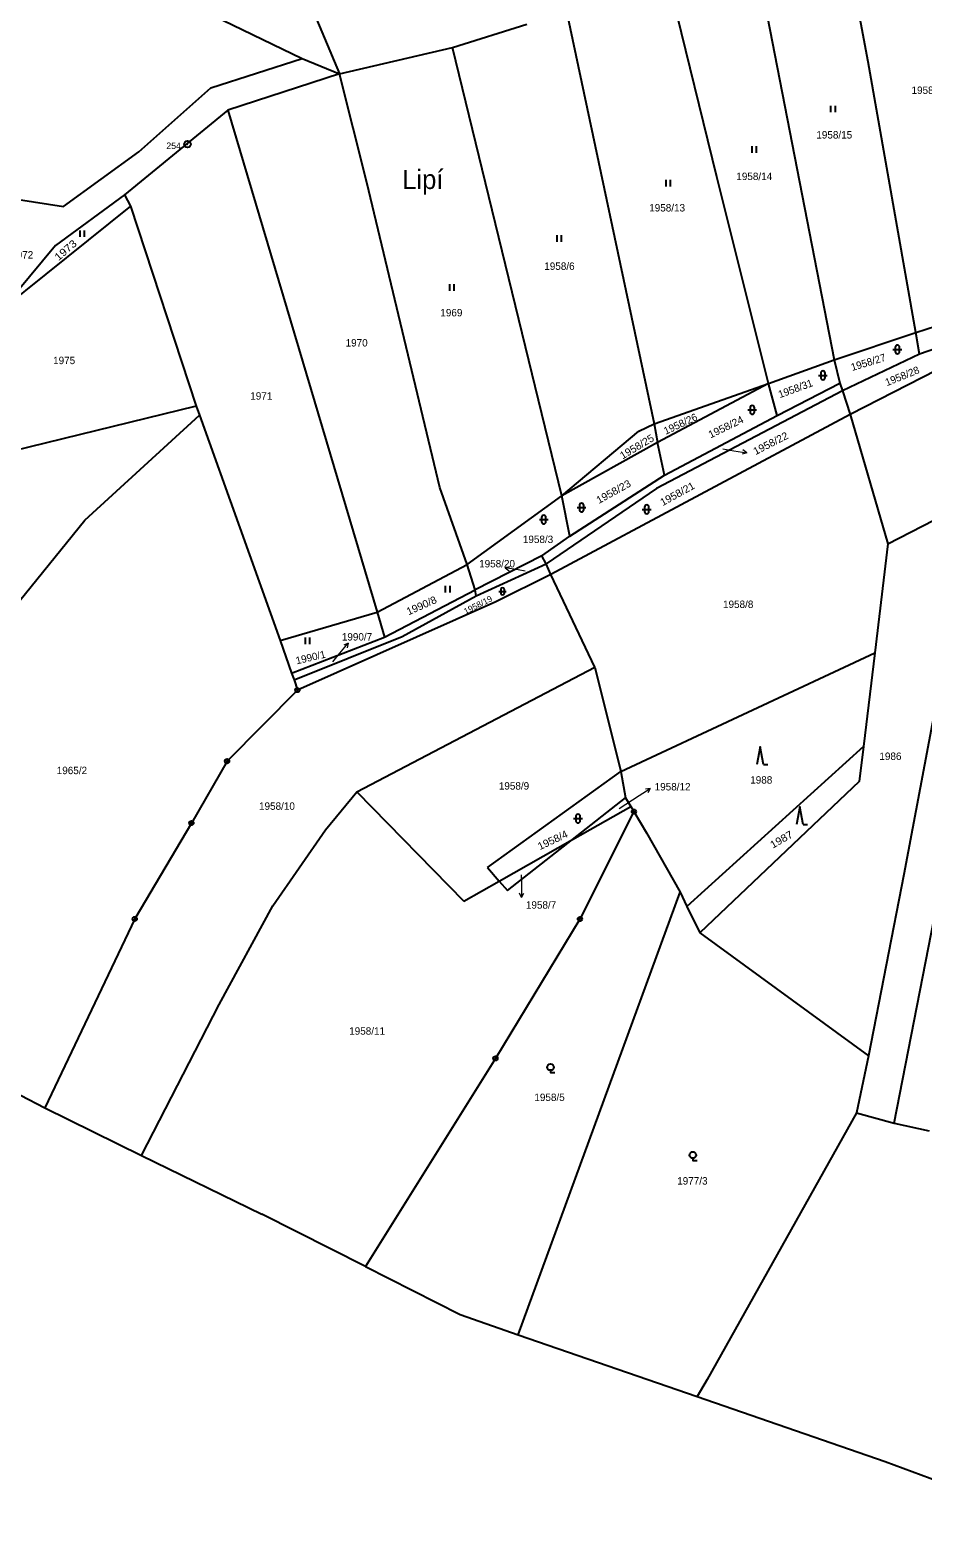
# Model space of a CAD drawing. Extents: x -820420 to -815896, y -1105820 to -1103643.
# Drawn here: x -817820.3 to -817615.8, y -1105643.5 to -1105298 of the extents above; entities that cross this region are included whole.
import ezdxf
from ezdxf.enums import TextEntityAlignment as Align

# ---------------------------------------------------------------- set-up
doc = ezdxf.new("R2010")
doc.units = 0
doc.header["$LTSCALE"] = 0.68
for name, color, linetype, lineweight in [('1', 7, 'Continuous', 25), ('3', 7, 'Continuous', 25), ('7', 7, 'Continuous', 13), ('8', 7, 'Continuous', 25)]:
    doc.layers.add(name, color=color, linetype=linetype, lineweight=lineweight)
doc.layers.add('2', color=7, linetype='Continuous')

msp = doc.modelspace()

# ---------------------------------------------------------------- linework, layer by layer
at = {"layer": '1'}
for p, q in [((-817770.8, -1105257.05), (-817749.4, -1105308.01)), ((-817628.28, -1105305.24), (-817636.42, -1105261.82)), ((-817662.95, -1105331.59), (-817675.54, -1105280.33)), ((-817803.5, -1105282.4), (-817758.02, -1105304.52)), ((-817697.9, -1105291.5), (-817677.3, -1105388.24)), ((-817723.54, -1105302), (-817706.51, -1105296.61)), ((-817749.4, -1105308.01), (-817723.54, -1105302)), ((-817698.51, -1105404.68), (-817723.54, -1105302)), ((-817778.95, -1105311.22), (-817758.02, -1105304.52)), ((-817758.02, -1105304.52), (-817749.4, -1105308.01)), ((-817617.36, -1105367.25), (-817628.28, -1105305.24)), ((-817749.4, -1105308.01), (-817775.03, -1105316.3)), ((-817743.19, -1105332.91), (-817749.4, -1105308.01)), ((-817795.42, -1105325.91), (-817778.95, -1105311.22)), ((-817775.03, -1105316.3), (-817798.7, -1105335.71)), ((-817775.03, -1105316.3), (-817740.83, -1105431.41)), ((-817812.7, -1105338.43), (-817795.42, -1105325.91)), ((-817726.41, -1105402.79), (-817743.19, -1105332.91)), ((-817651.1, -1105378.94), (-817662.95, -1105331.59)), ((-817823, -1105336.84), (-817812.7, -1105338.43)), ((-817798.7, -1105335.71), (-817814.49, -1105347.38)), ((-817798.7, -1105335.71), (-817797.31, -1105338.32)), ((-817797.31, -1105338.32), (-817826.4, -1105361.74)), ((-817797.31, -1105338.32), (-817782.25, -1105384.13)), ((-817814.49, -1105347.38), (-817826.4, -1105361.74)), ((-817617.36, -1105367.25), (-817592.59, -1105359.31)), ((-817592.07, -1105363.77), (-817616.48, -1105372.23)), ((-817636.05, -1105373.55), (-817617.36, -1105367.25)), ((-817616.48, -1105372.23), (-817617.36, -1105367.25)), ((-817651.1, -1105378.94), (-817636.05, -1105373.55)), ((-817616.48, -1105372.23), (-817634.14, -1105380.66)), ((-817609.28, -1105374.23), (-817632.39, -1105386.09)), ((-817649.14, -1105386.32), (-817634.78, -1105378.88)), ((-817634.78, -1105378.88), (-817634.14, -1105380.66)), ((-817677.3, -1105388.24), (-817651.1, -1105378.94)), ((-817634.14, -1105380.66), (-817676.81, -1105403.03)), ((-817651.1, -1105378.94), (-817676.56, -1105392.48)), ((-817649.14, -1105386.32), (-817651.1, -1105378.94)), ((-817634.14, -1105380.66), (-817632.39, -1105386.09)), ((-817782.25, -1105384.13), (-817857.97, -1105402.72)), ((-817782.25, -1105384.13), (-817781.55, -1105386.25)), ((-817807.78, -1105410.27), (-817781.55, -1105386.25)), ((-817781.55, -1105386.25), (-817763.01, -1105437.87)), ((-817632.39, -1105386.09), (-817700.97, -1105422.74)), ((-817680.87, -1105389.9), (-817677.3, -1105388.24)), ((-817677.3, -1105388.24), (-817676.56, -1105392.48)), ((-817674.95, -1105399.99), (-817649.14, -1105386.32)), ((-817632.39, -1105386.09), (-817623.79, -1105415.7)), ((-817698.51, -1105404.68), (-817680.87, -1105389.9)), ((-817676.56, -1105392.48), (-817698.51, -1105404.68)), ((-817674.95, -1105399.99), (-817676.56, -1105392.48)), ((-817720.2, -1105420.42), (-817726.41, -1105402.79)), ((-817676.81, -1105403.03), (-817702.11, -1105420.3)), ((-817696.66, -1105413.94), (-817674.95, -1105399.99)), ((-817720.2, -1105420.42), (-817698.51, -1105404.68)), ((-817696.66, -1105413.94), (-817698.51, -1105404.68)), ((-817623.79, -1105415.7), (-817603.95, -1105405.51)), ((-817603.95, -1105405.51), (-817620.11, -1105491.48)), ((-817825.59, -1105432.28), (-817807.78, -1105410.27)), ((-817703.07, -1105418.5), (-817696.66, -1105413.94)), ((-817623.79, -1105415.7), (-817626.73, -1105440.73)), ((-817703.07, -1105418.5), (-817718.33, -1105426.29)), ((-817718.08, -1105427.61), (-817702.11, -1105420.3)), ((-817702.11, -1105420.3), (-817703.07, -1105418.5)), ((-817700.97, -1105422.74), (-817702.11, -1105420.3)), ((-817740.83, -1105431.41), (-817720.2, -1105420.42)), ((-817718.33, -1105426.29), (-817720.2, -1105420.42)), ((-817700.97, -1105422.74), (-817713.64, -1105429.02)), ((-817690.91, -1105443.96), (-817700.97, -1105422.74)), ((-817718.08, -1105427.61), (-817718.33, -1105426.29)), ((-817713.64, -1105429.02), (-817759.09, -1105449.24)), ((-817735.11, -1105436.92), (-817718.08, -1105427.61)), ((-817763.01, -1105437.87), (-817740.83, -1105431.41)), ((-817740.83, -1105431.41), (-817739.13, -1105437.14)), ((-817759.81, -1105446.9), (-817735.11, -1105436.92)), ((-817763.01, -1105437.87), (-817760.41, -1105445.32)), ((-817684.95, -1105467.92), (-817626.73, -1105440.73)), ((-817626.73, -1105440.73), (-817629.37, -1105462.17)), ((-817745.5, -1105472.51), (-817690.91, -1105443.96)), ((-817690.91, -1105443.96), (-817684.95, -1105467.92)), ((-817759.09, -1105449.24), (-817775.21, -1105465.52)), ((-817622.3, -1105548.46), (-817604.55, -1105457.26)), ((-817629.37, -1105462.17), (-817669.86, -1105498.83)), ((-817629.37, -1105462.17), (-817630.37, -1105470.21)), ((-817775.21, -1105465.52), (-817783.38, -1105479.69)), ((-817715.53, -1105489.87), (-817684.95, -1105467.92)), ((-817684.95, -1105467.92), (-817683.89, -1105473.93)), ((-817630.37, -1105470.21), (-817666.89, -1105504.89)), ((-817752.68, -1105481.28), (-817745.5, -1105472.51)), ((-817745.5, -1105472.51), (-817720.91, -1105497.58)), ((-817696.06, -1105483.49), (-817683.89, -1105473.93)), ((-817683.89, -1105473.93), (-817682.67, -1105475.9)), ((-817696.06, -1105483.49), (-817682.67, -1105475.9)), ((-817681.95, -1105477.08), (-817694.33, -1105501.71)), ((-817682.67, -1105475.9), (-817681.95, -1105477.08)), ((-817681.95, -1105477.08), (-817679.05, -1105481.94)), ((-817783.38, -1105479.69), (-817796.35, -1105501.67)), ((-817764.68, -1105498.65), (-817752.68, -1105481.28)), ((-817679.05, -1105481.94), (-817671.37, -1105495.53)), ((-817712.82, -1105492.99), (-817696.06, -1105483.49)), ((-817710.93, -1105495.17), (-817696.06, -1105483.49)), ((-817715.53, -1105489.87), (-817712.82, -1105492.99)), ((-817620.11, -1105491.48), (-817628.17, -1105533.03)), ((-817720.91, -1105497.58), (-817712.82, -1105492.99)), ((-817712.82, -1105492.99), (-817710.93, -1105495.17)), ((-817708.49, -1105596.94), (-817671.37, -1105495.53)), ((-817671.37, -1105495.53), (-817669.86, -1105498.83)), ((-817777.02, -1105521.29), (-817764.68, -1105498.65)), ((-817669.86, -1105498.83), (-817666.89, -1105504.89)), ((-817796.35, -1105501.67), (-817816.97, -1105544.94)), ((-817694.33, -1105501.71), (-817713.69, -1105533.64)), ((-817666.89, -1105504.89), (-817628.17, -1105533.03)), ((-817794.81, -1105555.85), (-817777.02, -1105521.29)), ((-817844.82, -1105530.45), (-817816.97, -1105544.94)), ((-817713.69, -1105533.64), (-817743.47, -1105581.35)), ((-817628.17, -1105533.03), (-817630.93, -1105546.11)), ((-817816.97, -1105544.94), (-817794.81, -1105555.85)), ((-817630.93, -1105546.11), (-817665.17, -1105607.22)), ((-817630.93, -1105546.11), (-817622.3, -1105548.46)), ((-817622.3, -1105548.46), (-817614.32, -1105550.25)), ((-817794.81, -1105555.85), (-817767.22, -1105569.35)), ((-817743.47, -1105581.35), (-817767.22, -1105569.35)), ((-817743.47, -1105581.35), (-817721.77, -1105592.34)), ((-817721.77, -1105592.34), (-817708.49, -1105596.94)), ((-817708.49, -1105596.94), (-817667.45, -1105611.14)), ((-817665.17, -1105607.22), (-817667.45, -1105611.14)), ((-817667.45, -1105611.14), (-817624.36, -1105625.97)), ((-817624.36, -1105625.97), (-817577.74, -1105643.5))]:
    msp.add_line(p, q, dxfattribs=at)
for points in [[(-817655.9, -1105271.52), (-817636.05, -1105373.55), (-817634.78, -1105378.88)], [(-817760.41, -1105445.32), (-817739.13, -1105437.14), (-817718.33, -1105426.29)], [(-817760.41, -1105445.32), (-817759.81, -1105446.9), (-817759.09, -1105449.24)]]:
    msp.add_lwpolyline(points, dxfattribs=at)
at = {"layer": '3'}
for p, q in [((-817636.801, -1105316.83), (-817636.801, -1105315.33)), ((-817635.8, -1105316.83), (-817635.8, -1105315.33)), ((-817654.901, -1105326.12), (-817654.901, -1105324.62)), ((-817653.9, -1105326.12), (-817653.9, -1105324.62)), ((-817674.581, -1105333.81), (-817674.581, -1105332.31)), ((-817673.58, -1105333.81), (-817673.58, -1105332.31)), ((-817808.871, -1105345.4), (-817808.871, -1105343.9)), ((-817807.87, -1105345.4), (-817807.87, -1105343.9)), ((-817699.541, -1105346.47), (-817699.541, -1105344.97)), ((-817698.54, -1105346.47), (-817698.54, -1105344.97)), ((-817724.181, -1105357.72), (-817724.181, -1105356.22)), ((-817723.18, -1105357.72), (-817723.18, -1105356.22)), ((-817622.591, -1105371.161), (-817620.589, -1105371.161)), ((-817622.091, -1105370.661), (-817622.091, -1105371.662)), ((-817621.089, -1105371.662), (-817621.089, -1105370.661)), ((-817639.651, -1105377.101), (-817637.649, -1105377.101)), ((-817639.151, -1105376.601), (-817639.151, -1105377.602)), ((-817638.149, -1105377.602), (-817638.149, -1105376.601)), ((-817655.861, -1105385.031), (-817653.859, -1105385.031)), ((-817655.361, -1105384.531), (-817655.361, -1105385.532)), ((-817654.359, -1105385.532), (-817654.359, -1105384.531)), ((-817703.121, -1105409.651), (-817703.121, -1105410.652)), ((-817702.119, -1105410.652), (-817702.119, -1105409.651)), ((-817694.971, -1105407.411), (-817692.969, -1105407.411)), ((-817694.471, -1105406.911), (-817694.471, -1105407.912)), ((-817693.469, -1105407.912), (-817693.469, -1105406.911)), ((-817680.041, -1105407.811), (-817678.039, -1105407.811)), ((-817679.541, -1105407.311), (-817679.541, -1105408.312)), ((-817678.539, -1105408.312), (-817678.539, -1105407.311)), ((-817703.621, -1105410.151), (-817701.619, -1105410.151)), ((-817725.111, -1105426.84), (-817725.111, -1105425.34)), ((-817724.11, -1105426.84), (-817724.11, -1105425.34)), ((-817712.891, -1105426.601), (-817711.249, -1105426.601)), ((-817712.48, -1105426.19), (-817712.48, -1105427.011)), ((-817711.66, -1105427.011), (-817711.66, -1105426.19)), ((-817757.261, -1105438.68), (-817757.261, -1105437.18)), ((-817756.26, -1105438.68), (-817756.26, -1105437.18)), ((-817652.29, -1105466.25), (-817651.294, -1105466.25)), ((-817695.781, -1105478.671), (-817693.779, -1105478.671)), ((-817695.281, -1105478.171), (-817695.281, -1105479.172)), ((-817694.279, -1105479.172), (-817694.279, -1105478.171)), ((-817643.17, -1105480.02), (-817642.174, -1105480.02))]:
    msp.add_line(p, q, dxfattribs=at)
for points in [[(-817652.29, -1105466.25), (-817653.04, -1105462.25), (-817653.79, -1105466.25)], [(-817643.17, -1105480.02), (-817643.92, -1105476.02), (-817644.67, -1105480.02)], [(-817701.08, -1105536.362), (-817701.08, -1105536.86), (-817700.079, -1105536.86)], [(-817668.44, -1105556.522), (-817668.44, -1105557.02), (-817667.439, -1105557.02)]]:
    msp.add_lwpolyline(points, dxfattribs=at)
for centre in [(-817701.0793, -1105535.6109), (-817668.4393, -1105555.7709)]:
    msp.add_circle(centre, 0.75, dxfattribs=at)
for centre, radius, start, end in [((-817621.59, -1105370.6609), 0.5, 0, 180), ((-817621.59, -1105371.6609), 0.5, 180, 359.98789), ((-817638.65, -1105376.6009), 0.5, 0, 180), ((-817638.65, -1105377.6009), 0.5, 180, 359.98789), ((-817654.86, -1105384.5309), 0.5, 0, 180), ((-817654.86, -1105385.5309), 0.5, 180, 359.98789), ((-817693.97, -1105406.9109), 0.5, 0, 180), ((-817702.62, -1105409.6509), 0.5, 0, 180), ((-817693.97, -1105407.9109), 0.5, 180, 359.98789), ((-817679.04, -1105407.3109), 0.5, 0, 180), ((-817679.04, -1105408.3109), 0.5, 180, 359.98789), ((-817702.62, -1105410.6509), 0.5, 180, 359.98789), ((-817712.07, -1105426.1907), 0.41, 0, 180), ((-817712.07, -1105427.0107), 0.41, 180, 359.98789), ((-817694.78, -1105478.1709), 0.5, 0, 180), ((-817694.78, -1105479.1709), 0.5, 180, 359.98789)]:
    msp.add_arc(centre, radius, start, end, dxfattribs=at)
at = {"layer": '7'}
for p, q in [((-817656.066, -1105394.839), (-817656.977, -1105394.188)), ((-817711.464, -1105421.231), (-817710.553, -1105421.882)), ((-817747.461, -1105438.458), (-817748.481, -1105438.921)), ((-817678.223, -1105471.786), (-817679.336, -1105471.911)), ((-817707.698, -1105496.751), (-817707.214, -1105495.74))]:
    msp.add_line(p, q, dxfattribs=at)
for points in [[(-817661.61, -1105393.95), (-817659.03, -1105394.37), (-817656.066, -1105394.839), (-817657.133, -1105395.177)], [(-817706.9, -1105421.96), (-817708.5, -1105421.7), (-817711.464, -1105421.231), (-817710.397, -1105420.893)], [(-817750.96, -1105442.76), (-817749.35, -1105440.79), (-817747.461, -1105438.458), (-817747.703, -1105439.551)], [(-817685.32, -1105476.36), (-817680.74, -1105473.42), (-817678.223, -1105471.786), (-817678.79, -1105472.751)], [(-817707.78, -1105491.57), (-817707.75, -1105493.75), (-817707.698, -1105496.751), (-817708.216, -1105495.758)]]:
    msp.add_lwpolyline(points, dxfattribs=at)
at = {"layer": '8'}
for centre, radius in [((-817784.28, -1105324.1298), 0.75), ((-817784.28, -1105324.1298), 0.03), ((-817759.09, -1105449.2399), 0.5), ((-817759.09, -1105449.2399), 0.0303), ((-817775.21, -1105465.5199), 0.5), ((-817775.21, -1105465.5199), 0.0303), ((-817681.95, -1105477.0799), 0.5), ((-817681.95, -1105477.0799), 0.0303), ((-817783.38, -1105479.6899), 0.5), ((-817783.38, -1105479.6899), 0.0303), ((-817796.35, -1105501.6699), 0.5), ((-817796.35, -1105501.6699), 0.0303), ((-817694.33, -1105501.7099), 0.5), ((-817694.33, -1105501.7099), 0.0303), ((-817713.69, -1105533.6399), 0.5), ((-817713.69, -1105533.6399), 0.0303)]:
    msp.add_circle(centre, radius, dxfattribs=at)

# ---------------------------------------------------------------- texts
at = {"layer": '2'}
for s, p in [('1958/17', (-817614.239, -1105312.615)), ('1958/15', (-817636.049, -1105322.835)), ('1958/14', (-817654.389, -1105332.355)), ('1958/13', (-817674.349, -1105339.555)), ('1972', (-817822.15, -1105350.335)), ('1958/6', (-817699.03, -1105352.935)), ('1969', (-817723.8, -1105363.585)), ('1970', (-817745.51, -1105370.495)), ('1975', (-817812.54, -1105374.535)), ('1971', (-817767.36, -1105382.675)), ('1958/3', (-817703.94, -1105415.535)), ('1958/8', (-817658.07, -1105430.415)), ('1986', (-817623.18, -1105465.235)), ('1965/2', (-817810.76, -1105468.495)), ('1958/9', (-817709.45, -1105472.035)), ('1988', (-817652.78, -1105470.665)), ('1958/10', (-817763.769, -1105476.665)), ('1958/11', (-817743.109, -1105528.205)), ('1958/5', (-817701.3, -1105543.395)), ('1977/3', (-817668.57, -1105562.545))]:
    msp.add_text(s, height=1.7, dxfattribs=at).set_placement(p, align=Align.CENTER)
for s, height, rotation, width, p in [('1973', 1.7, 41, 1.15, (-817811.6461, -1105349.053)), ('1958/24', 1.7, 26, 1.05, (-817660.5236, -1105389.6888)), ('1958/25', 1.7, 31, 1.05, (-817680.8478, -1105394.1803)), ('1958/22', 1.7, 27, 1.05, (-817650.2404, -1105393.4381)), ('1958/23', 1.7, 29, 1.05, (-817686.2241, -1105404.5046)), ('1958/21', 1.7, 29, 1.05, (-817671.5941, -1105405.0046)), ('1990/8', 1.7, 24, 1.05, (-817730.2902, -1105430.6297)), ('1958/19', 1.386, 27, 1.05, (-817717.3921, -1105430.3272)), ('1958/4', 1.7, 25, 1.05, (-817700.2177, -1105484.3799)), ('1987', 1.7, 30, 1.1, (-817647.74, -1105484.2024))]:
    msp.add_text(s, height=height, rotation=rotation, dxfattribs=dict(at, width=width)).set_placement(p, align=Align.CENTER)
for s, rotation, p in [('1958/27', 17, (-817628.0085, -1105374.9175)), ('1958/28', 22, (-817620.1684, -1105378.0578)), ('1958/31', 20, (-817644.6562, -1105380.9349)), ('1958/26', 25, (-817670.9377, -1105388.9996)), ('1990/1', 13, (-817755.8562, -1105442.5608))]:
    msp.add_text(s, height=1.7, rotation=rotation, dxfattribs=at).set_placement(p, align=Align.CENTER)
msp.add_text('1958/20', height=1.7, dxfattribs=at).set_placement((-817709.22, -1105421.115), align=Align.RIGHT)
for s, p in [('1990/7', (-817748.9, -1105437.875)), ('1958/12', (-817677.21, -1105472.225)), ('1958/7', (-817706.72, -1105499.315))]:
    msp.add_text(s, height=1.7, dxfattribs=at).set_placement(p)
at = {"layer": '7'}
msp.add_text('Lipí', height=4.4, dxfattribs=at).set_placement((-817730.339, -1105334.41), align=Align.CENTER)
at = {"layer": '8'}
msp.add_text('254', height=1.5, dxfattribs=at).set_placement((-817785.779, -1105325.247), align=Align.RIGHT)

doc.saveas('drawing.dxf')
